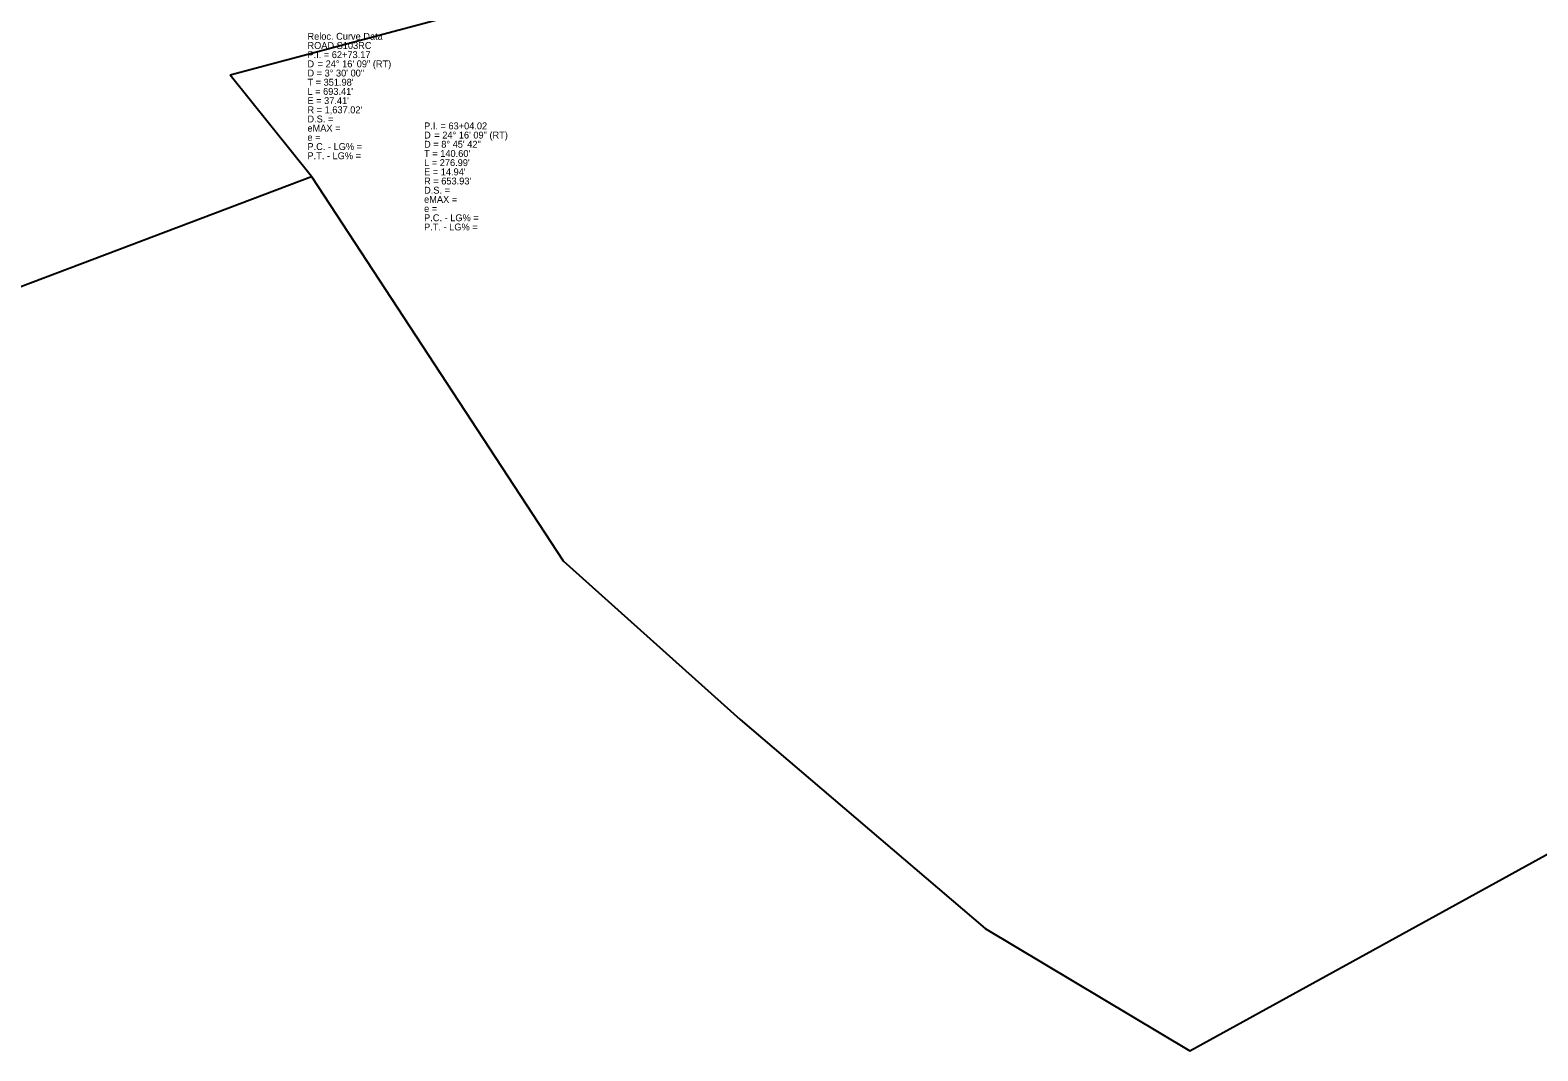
# Model space of a CAD drawing. Extents: x 1964982 to 1970527, y 1116335 to 1119906.
# Drawn here: x 1967680 to 1969321, y 1116335 to 1117446 of the extents above; entities that cross this region are included whole.
import ezdxf

# ---------------------------------------------------------------- set-up
doc = ezdxf.new("R2010")
doc.units = 0
doc.layers.add('RD_EX_DV_Prop', color=7, linetype='Continuous')
doc.layers.add('RD_HC_txCode', color=7, linetype='Continuous')

msp = doc.modelspace()

# ---------------------------------------------------------------- linework, layer by layer
at = {"layer": 'RD_EX_DV_Prop'}
for p, q in [((1968204.3, 1117478.1), (1967898.1, 1117396.7)), ((1967986.4, 1117286.2), (1967898.1, 1117396.7)), ((1967582.6, 1117133.3), (1967986.4, 1117286.2)), ((1967986.4, 1117286.2), (1968260.1, 1116868.2)), ((1968260.1, 1116868.2), (1968452.8, 1116695.3)), ((1968941.8, 1116334.8), (1969776.6, 1116794.1)), ((1968452.8, 1116695.3), (1968719.5, 1116468.1)), ((1968719.5, 1116468.1), (1968941.8, 1116334.8))]:
    msp.add_line(p, q, dxfattribs=at)

# ---------------------------------------------------------------- texts
at = {"layer": 'RD_HC_txCode'}
for s, p in [('Reloc. Curve Data', (1967982.1, 1117435.1)), ('ROAD S103RC', (1967982.1, 1117425.1)), ('P.I. = 62+73.17', (1967982.1, 1117415.1)), ('D', (1967982.1, 1117405.1)), ('D = 3%%d 30\' 00"', (1967982.1, 1117395.1)), ('    = 24%%d 16\' 09" (RT)', (1967982.1, 1117405.1)), ("T = 351.98'", (1967982.1, 1117385.1)), ("L = 693.41'", (1967982.1, 1117375.1)), ("E = 37.41'", (1967982.1, 1117365.1)), ("R = 1,637.02'", (1967982.1, 1117355.1)), ('D.S. =', (1967982.1, 1117345.1)), ('eMAX = ', (1967982.1, 1117335.1)), ('P.I. = 63+04.02', (1968109, 1117337.6)), ('D', (1968109, 1117327.6)), ('    = 24%%d 16\' 09" (RT)', (1968109, 1117327.6)), ('e = ', (1967982.1, 1117325.1)), ('P.C. - LG% = ', (1967982.1, 1117315.1)), ('D = 8%%d 45\' 42"', (1968109, 1117317.6)), ('P.T. - LG% = ', (1967982.1, 1117305.1)), ("T = 140.60'", (1968109, 1117307.6)), ("L = 276.99'", (1968109, 1117297.6)), ("E = 14.94'", (1968109, 1117287.6)), ("R = 653.93'", (1968109, 1117277.6)), ('D.S. = ', (1968109, 1117267.6)), ('eMAX = ', (1968109, 1117257.6)), ('e = ', (1968109, 1117247.6)), ('P.C. - LG% = ', (1968109, 1117237.6)), ('P.T. - LG% = ', (1968109, 1117227.6))]:
    msp.add_text(s, height=7.5, dxfattribs=at).set_placement(p)

doc.saveas('drawing.dxf')
